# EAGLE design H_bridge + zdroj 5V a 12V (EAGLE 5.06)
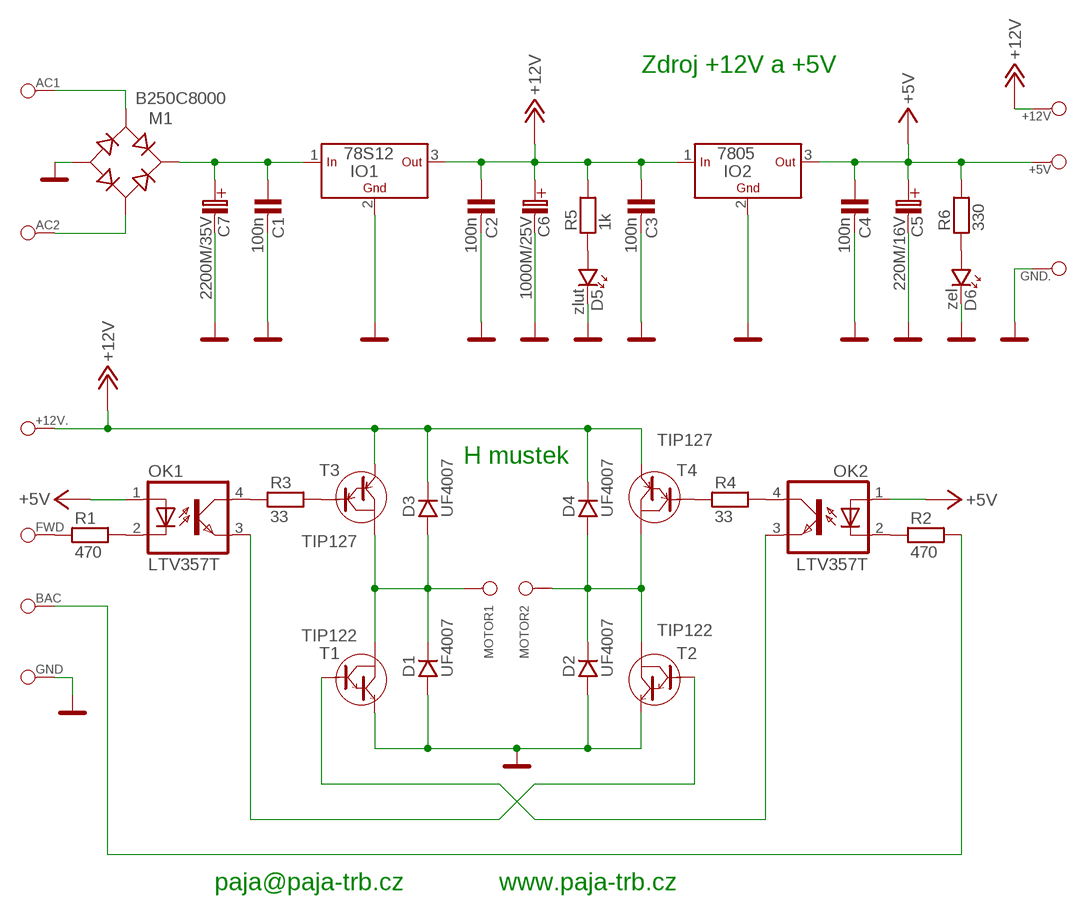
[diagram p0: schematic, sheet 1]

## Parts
+5V  WAGO256  [WAGO256]
+12V  WAGO256  [WAGO256]
+12V.  WAGO256  [WAGO256]
AC1  WAGO256  [WAGO256]
AC2  WAGO256  [WAGO256]
BAC  WAGO256  [WAGO256]
C1  100n  C-KERAMIK_SMD_1206  [1206]
C2  100n  C-KERAMIK_SMD_1206  [1206]
C3  100n  C-KERAMIK_SMD_1206  [1206]
C4  100n  C-KERAMIK_SMD_1206  [1206]
C5  220M/16V  [C_EL_3,5]
C6  1000M/25V  [C_EL_5+]
C7  2200M/35V  [C_EL_7,5]
D1  UF4007  D_10  [DO41]
D2  UF4007  D_10  [DO41]
D3  UF4007  D_10  [DO41]
D4  UF4007  D_10  [DO41]
D5  zlut  LED_3  [LED_3]
D6  zel  LED_3  [LED_3]
FWD  WAGO256  [WAGO256]
GND  WAGO256  [WAGO256]
GND.  WAGO256  [WAGO256]
IO1  78S12  78_STOJ_STOJ  [TO-220S]
IO2  7805  78_STOJ_STOJ  [TO-220S]
M1  B250C8000  D-MUSTEK_B250C8000  [DM_KBU]
MOTOR1  WAGO256  [WAGO256]
MOTOR2  WAGO256  [WAGO256]
OK1  LTV357T  LTV816S  [SMD4]
OK2  LTV357T  LTV816S  [SMD4]
R1  470  R_SMD_1206  [1206]
R2  470  R_SMD_1206  [1206]
R3  33  R_SMD_1206  [1206]
R4  33  R_SMD_1206  [1206]
R5  1k  R_SMD_1206  [1206]
R6  330  R_SMD_1206  [1206]
T1  TIP122  TIP122_STOJ  [TO-220S]
T2  TIP122  TIP122_STOJ  [TO-220S]
T3  TIP127  TIP127_STOJ  [TO-220S]
T4  TIP127  TIP127_STOJ  [TO-220S]

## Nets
+5V: +5V.1 C4.1 C5.C+(C_EL+) IO2.3(OUT) OK1.1(A) OK2.1(A) R6.2
+12V: +12V.1 +12V..1 C2.1 C3.1 C6.C+(C_EL+) D3.K D4.K IO1.3(OUT) IO2.1(IN) R5.2 T3.3(E) T4.3(E)
GND: C1.2 C2.2 C3.2 C4.2 C5.C-(C_EL-) C6.C-(C_EL-) C7.C-(C_EL-) D1.A D2.A D5.K D6.K GND.1 GND..1 IO1.2(GND) IO2.2(GND) M1.- T1.3(E) T2.3(E)
N$1: D1.K D3.A MOTOR1.1 T1.2(C) T3.2(C)
N$2: D2.K D4.A MOTOR2.1 T2.2(C) T4.2(C)
N$3: R3.2 T3.1(B)
N$4: OK1.2(C) R1.2
N$5: R4.1 T4.1(B)
N$6: OK1.4(COL) R3.1
N$7: OK2.4(COL) R4.2
N$8: D5.A R5.1
N$9: OK2.2(C) R2.1
N$10: D6.A R6.1
N$11: OK1.3(EMIT) T2.1(B)
N$12: OK2.3(EMIT) T1.1(B)
N$13: FWD.1 R1.1
N$14: BAC.1 R2.2
N$16: AC2.1 M1.AC2
N$17: AC1.1 M1.AC1
N$18: C1.1 C7.C+(C_EL+) IO1.1(IN) M1.+

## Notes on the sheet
- Zdroj +12V a +5V
- H mustek
- paja@paja-trb.cz | www.paja-trb.cz

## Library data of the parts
+5V +12V +12V. AC1 AC2 BAC FWD GND GND. MOTOR1 MOTOR2 = #PaJa_konektory:WAGO256: Konektor WAGO - RM 5,08mm - s packou
C1-C4 = #PaJa_31:C-KERAMIK: Kondenzator - keramicky
C5 = #PaJa_C-el_2:220M/16V
C6 = #PaJa_C-el_2:1000M/25V
C7 = #PaJa_C-el_2:2200M/35V
D1-D4 = #PaJa_31:D: Dioda - univerzální
D5 D6 = #PaJa_31:LED: LED - jednobarevna
IO1 IO2 = #PaJa_31:78??: Stabilizátor - 1A a 1,5A ?? - napeti => 05, 06, 08, 09, 12, 15, 18, 20, 24 => 1,5A ?? - napeti => 10, 12, 15, 18 => 1A S ?? - napeti => 05, 09, 10, 12, 15, 18, 24 => 2A T ?? - napeti => 05 => 3A
M1 = #PaJa_31:D-MUSTEK: Diodovy mustek - Graetz
OK1 OK2 = optocoupler:LTV816: OPTO COUPLER Source: LITEON, LTV816.pdf
R1-R6 = #PaJa_31:R: Rezistor
T1 T2 = #PaJa_31:TIP122: Tranzistor NPN - Darlington - Ic=5A, 100V
T3 T4 = #PaJa_31:TIP127: Tranzistor PNP - Darlington - Ic=5A, 100V

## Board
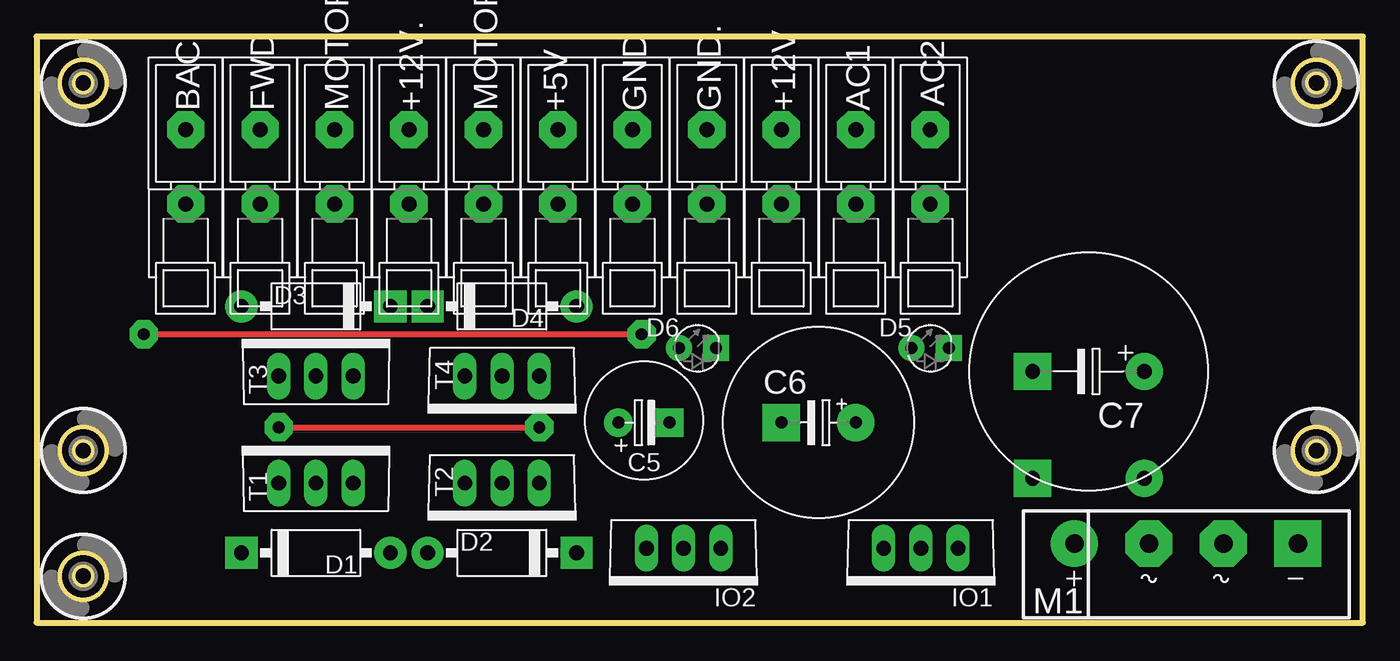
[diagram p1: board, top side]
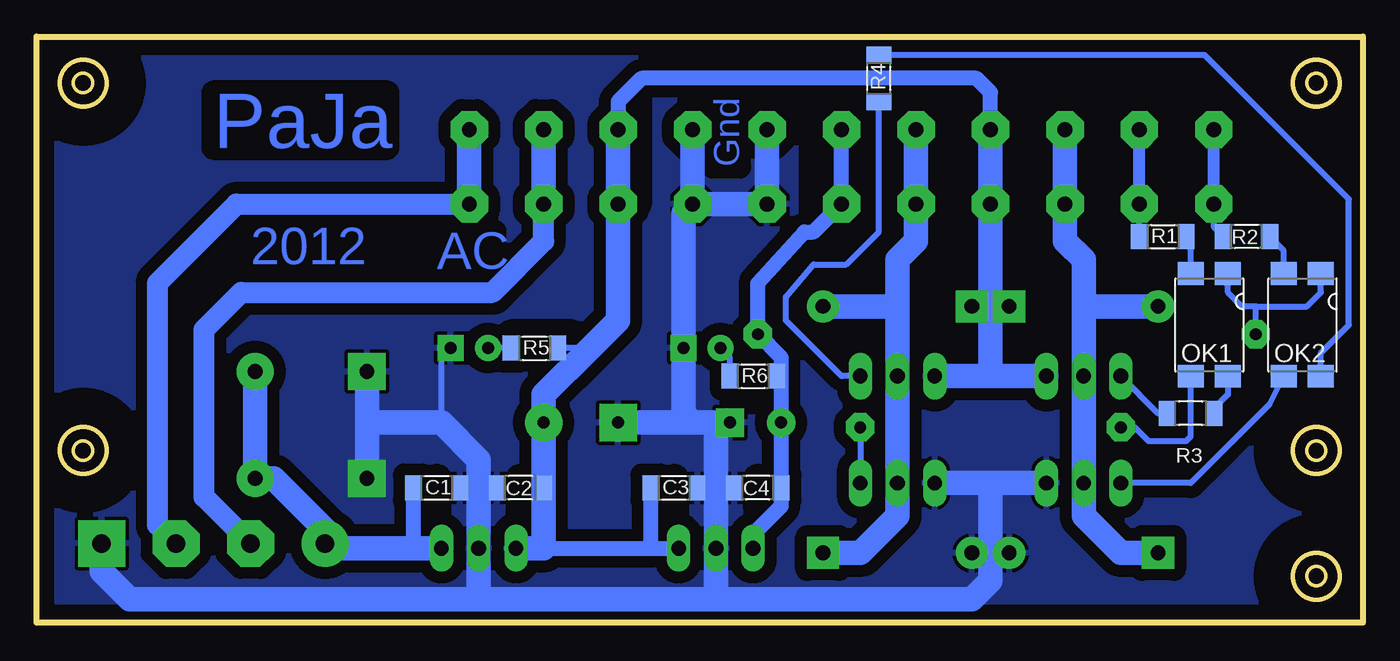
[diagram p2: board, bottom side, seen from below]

Size 90.47 x 39.99 mm. Coordinates in mm from the lower left corner, seen from the top.
Outline: 0,0 90.47,0 90.47,39.99 0,39.99 0,0
Copper layers (1*16): Top 0.035mm / dielectric 1.5mm / Bottom 0.035mm
Design rules "default": minimum track width 10mil, minimum drill 24mil, track to track 8mil, track to pad 8mil, pad to pad 8mil, via to via 8mil, smd to smd 8mil, copper to edge 40mil, drill to drill 8mil, minimum pad ring 10mil, minimum via ring 8mil, stop-mask expansion 4mil, vias tented up to drill 0mil, thermal gap 10mil
bRestrict: 8 lines

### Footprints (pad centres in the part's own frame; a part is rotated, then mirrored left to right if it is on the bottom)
WAGO256 = drill 1.016 pad 2.54 octagon: 1 0,0; A1 -5.08,0
1206 = smd 1.143 x 1.702: 1 -1.587,0; 2 1.587,0
C_EL_3,5 = drill 0.813 pad 1.93 round: C+ 0,0 | drill 0.813 pad 1.93 square: C- 3.493,0
C_EL_5+ = drill 0.813 pad 2.54 round: C+ -2.54,0 | drill 0.813 pad 2.54 square: C- 2.54,0
C_EL_7,5 = drill 1.016 pad 2.54 round: C+ -3.81,0 | drill 1.016 pad 2.54 square: C- 3.81,0
DO41 = drill 1.016 pad 2.184 round: A -5.08,0 | drill 1.016 pad 2.184 square: K 5.08,0
LED_3 = drill 0.813 pad 1.778 round: A -1.27,0 | drill 0.813 pad 1.778 square: K 1.27,0
TO-220S = drill 1.016 pad 1.6 long: 1 -2.54,0; 2 0,0; 3 2.54,0
DM_KBU = drill 1.27 pad 3.2 round: + -7.62,2.857 | drill 1.27 pad 3.2 square: - 7.62,2.857 | drill 1.27 pad 3.2 octagon: AC1 -2.54,2.857; AC2 2.54,2.857
SMD4 = smd 1.78 x 1.55: 1 -1.27,-3.5; 2 1.27,-3.5; 3 1.27,3.5; 4 -1.27,3.5
HOLE_3,0 = hole 3.2: 0,0

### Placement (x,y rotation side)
+5V  35.56,28.57 270 top
+12V  50.8,28.57 270 top
+12V.  25.4,28.57 270 top
AC1  55.88,28.57 270 top
AC2  60.96,28.57 270 top
BAC  10.16,28.57 270 top
C1  63.18,9.21 0 bottom
C2  57.47,9.21 180 bottom
C3  46.99,9.21 0 bottom
C4  41.27,9.21 180 bottom
C5  39.69,13.65 0 top
C6  53.34,13.65 180 top
C7  71.75,17.14 180 top
D1  19.05,4.76 180 top
D2  31.75,4.76 0 top
D3  19.05,21.59 0 top
D4  31.75,21.59 180 top
D5  60.96,18.73 0 top
D6  45.09,18.73 0 top
FWD  15.24,28.57 270 top
GND  40.64,28.57 270 top
GND.  45.72,28.57 270 top
IO1  60.33,5.08 180 top
IO2  44.13,5.08 180 top
M1  78.42,2.54 0 top
MOTOR1  20.32,28.57 270 top
MOTOR2  30.48,28.57 270 top
OK1  10.48,20.32 180 bottom
OK2  4.13,20.32 180 bottom
R1  13.65,26.35 0 bottom
R2  7.94,26.35 180 bottom
R3  11.75,14.29 180 bottom
R4  33.02,37.15 90 bottom
R5  56.52,18.73 0 bottom
R6  41.59,16.83 0 bottom
T1  19.05,9.53 0 top
T2  31.75,9.53 180 top
T3  19.05,16.83 0 top
T4  31.75,16.83 180 top
U$1  [HOLE_3,0]  3.17,3.17 0 top
U$2  [HOLE_3,0]  87.31,11.75 0 top
U$3  [HOLE_3,0]  87.31,36.83 0 top
U$4  [HOLE_3,0]  3.17,36.83 0 top
U$5  [HOLE_3,0]  3.17,11.75 0 top

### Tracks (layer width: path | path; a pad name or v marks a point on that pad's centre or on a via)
+5V  (via drill 0.81 pad 1.93)
  Top 0.406: v7.3,19.68 v41.27,19.68
  Bottom 0.406: 39.69,16.83 R6.2 | OK1.1 9.21,22.54 8.26,21.59 7.3,21.59 | 7.3,21.59 3.81,21.59 2.86,22.54 OK2.1 | v7.3,19.68 7.3,21.59
  Bottom 1.016: IO2.3 41.59,6.03 39.69,7.94 C4.1 C5.C+ 39.69,16.83 39.69,18.1 v41.27,19.68 41.27,23.18 38.1,26.67 37.47,26.67 +5V.1 35.56,33.66
+12V
  Bottom 0.406: 52.7,18.73 R5.2
  Bottom 1.016: 25.4,33.66 25.4,36.2 26.35,37.15 49.21,37.15 50.8,35.56 50.8,33.66 | 48.9,5.08 IO2.1 | 55.88,5.08 48.9,5.08 | C3.1 48.58,5.4 48.9,5.08
  Bottom 1.676: 25.4,21.59 D3.K | 25.4,16.83 25.4,21.59 | 25.4,21.59 +12V..1 25.4,33.66 | 25.4,16.83 T4.3 | T3.3 25.4,16.83 | 25.4,21.59 D4.K | IO1.3 55.88,5.08 C2.1 C6.C+ 55.88,15.56 52.7,18.73 50.8,20.64 +12V.1 50.8,33.66
GND  (via drill 1 pad 2.54)
  Bottom 0.406: D5.K 62.87,18.1 62.87,13.65
  Bottom 1.016: C2.2 60.33,9.21 C1.2 | C4.2 44.13,9.21 C3.2
  Bottom 1.676: 25.4,9.53 T1.3 | 25.4,9.53 T2.3 | D1.A 25.4,4.76 | 25.4,4.76 D2.A | 25.4,4.76 25.4,9.53 | 25.4,4.76 25.4,2.86 26.67,1.59 44.13,1.59 | GND..1 45.72,33.66 | 44.13,1.59 60.33,1.59 | 44.13,1.59 IO2.2 44.13,9.21 44.13,13.65 | 60.33,1.59 IO1.2 60.33,9.21 60.33,11.11 62.87,13.65 67.94,13.65 | 44.13,13.65 C5.C- | 44.13,13.65 45.72,13.65 | 45.72,13.65 C6.C- | 45.72,13.65 46.35,14.29 D6.K 46.35,27.94 GND..1 | 67.94,13.65 C7.C- | 60.33,1.59 84.14,1.59 86.04,3.49 M1.- | GND..1 GND.1 40.64,33.66 | 67.94,13.65 v67.94,9.84
  pour Bottom (isolate 0.813): 0,40.01 90.49,40.01 90.49,0 0,0
N$1
  Bottom 1.676: 19.05,21.59 T3.2 T1.2 19.05,7.3 16.51,4.76 D1.K | 20.32,33.66 MOTOR1.1 20.32,26.04 19.05,24.77 19.05,21.91 19.05,21.59 | 19.05,21.59 D3.A
N$2
  Bottom 1.676: 31.75,21.59 T4.2 T2.2 31.75,7.3 34.29,4.76 D2.K | 31.75,21.59 31.75,24.77 30.48,26.04 MOTOR2.1 30.48,33.66 | 31.75,21.59 D4.A
N$3
  Bottom 0.406: T3.1 13.97,14.29 R3.2
N$4
  Bottom 0.406: R1.2 11.75,26.04 OK1.2
N$5
  Bottom 0.406: T4.1 35.56,16.83 39.37,20.64 39.37,22.23 37.47,24.45 35.24,24.45 33.02,26.67 R4.1
N$6
  Bottom 0.406: R3.1 10.16,14.61 9.21,15.56 OK1.4
N$7
  Bottom 0.406: R4.2 10.79,38.73 0.95,28.89 0.95,20.32 2.86,18.41 OK2.4
N$8
  Bottom 0.406: R5.1 D5.A
N$9
  Bottom 0.406: R2.1 5.4,25.4 OK2.2
N$10
  Bottom 0.406: R6.1 43.18,18.1 D6.A
N$11  (via drill 0.81 pad 1.93)
  Top 0.406: v16.51,13.34 v34.29,13.34
  Bottom 0.406: OK1.3 11.75,12.7 12.06,12.38 14.61,12.38 15.56,13.34 v16.51,13.34 | v34.29,13.34 T2.1
N$12
  Bottom 0.406: OK2.3 6.35,14.92 11.75,9.53 T1.1
N$13
  Bottom 0.406: R1.1 FWD.1
  Bottom 0.813: FWD.1 15.24,33.66
N$14
  Bottom 0.406: R2.2 10.16,26.99 BAC.1
  Bottom 0.813: BAC.1 10.16,33.66
N$16
  Bottom 1.422: M1.AC2 82.23,6.67 82.23,23.18 76.83,28.57 AC2.1
  Bottom 1.676: AC2.1 60.96,33.66
N$17
  Bottom 1.422: M1.AC1 79.06,8.57 79.06,20 76.52,22.54 59.37,22.54 55.88,26.04 AC1.1
  Bottom 1.676: AC1.1 55.88,33.66
N$18  (via drill 1 pad 2.54)
  Bottom 1.016: 64.77,5.08 C1.1
  Bottom 1.676: C7.C+ v75.56,9.84 74.3,9.84 70.8,6.35 M1.+ 70.48,5.08 64.77,5.08 IO1.1

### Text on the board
Bottom: PaJa | Gnd | AC | 2012
PaJa: www.paja-trb.unas.cz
